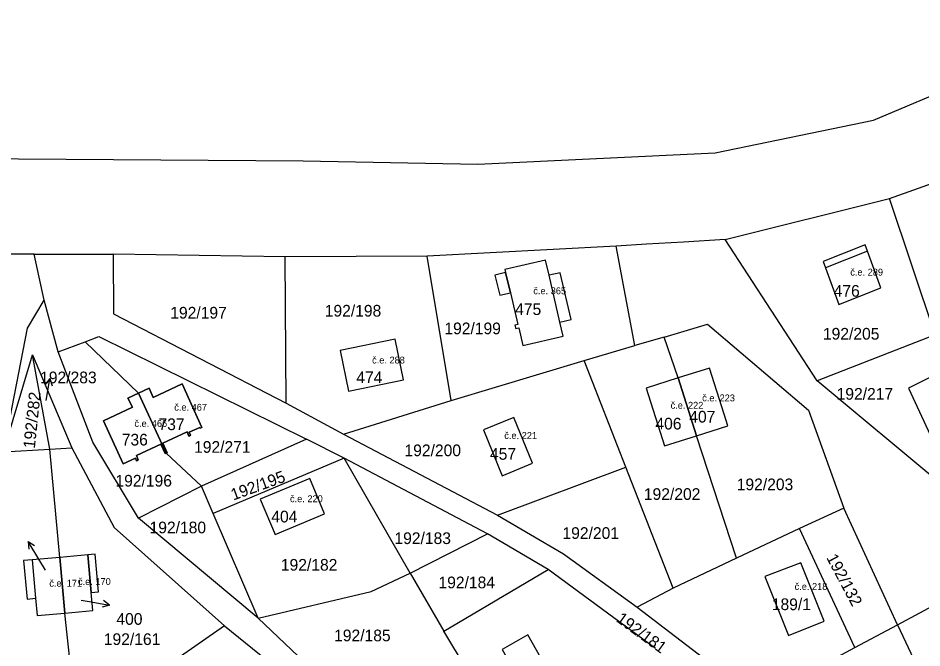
# Model space of a CAD drawing. Extents: x -887272 to -880188, y -1026687 to -1021896.
# Drawn here: x -882333.3 to -882201.9, y -1024111.9 to -1024020.3 of the extents above; entities that cross this region are included whole.
import ezdxf

# ---------------------------------------------------------------- set-up
doc = ezdxf.new("R2010")
doc.units = 0
for name, color, linetype in [('Definiční body', 7, 'Continuous'), ('Hranice parcel', 7, 'Continuous'), ('Parcelní čísla', 7, 'Continuous'), ('Polygon budovy', 7, 'Continuous'), ('Pop  PČ popisy', 7, 'Continuous'), ('Vnitřní kresba', 7, 'Continuous')]:
    doc.layers.add(name, color=color, linetype=linetype)

msp = doc.modelspace()

# ---------------------------------------------------------------- linework, layer by layer
at = {"layer": 'Hranice parcel'}
for p, q in [((-882206.58, -1024046.52), (-882188.26, -1024039.89)), ((-882230.46, -1024052.45), (-882206.58, -1024046.52)), ((-882199.93, -1024066.33), (-882206.58, -1024046.52)), ((-882217.07, -1024073.03), (-882230.46, -1024052.45)), ((-882246.33, -1024053.44), (-882273.78, -1024054.86)), ((-882243.61, -1024067.89), (-882246.33, -1024053.44)), ((-882330.93, -1024054.59), (-882336.63, -1024054.59)), ((-882330.93, -1024054.59), (-882319.43, -1024054.58)), ((-882329.46, -1024061.27), (-882330.93, -1024054.59)), ((-882294.43, -1024054.96), (-882319.43, -1024054.58)), ((-882273.78, -1024054.86), (-882294.43, -1024054.96)), ((-882294.27, -1024076.26), (-882294.43, -1024054.96)), ((-882270.28, -1024075.87), (-882273.78, -1024054.86)), ((-882327.43, -1024068.82), (-882329.46, -1024061.27)), ((-882239.34, -1024066.64), (-882243.61, -1024067.89)), ((-882237.27, -1024072.6), (-882239.34, -1024066.64)), ((-882199.93, -1024066.33), (-882217.07, -1024073.03)), ((-882327.43, -1024068.82), (-882323.51, -1024067.33)), ((-882315.74, -1024074.82), (-882323.51, -1024067.33)), ((-882250.94, -1024070.04), (-882243.61, -1024067.89)), ((-882335.35, -1024083.33), (-882331.18, -1024069.25)), ((-882328.64, -1024082.94), (-882331.18, -1024069.25)), ((-882331.18, -1024069.25), (-882325.42, -1024082.75)), ((-882270.28, -1024075.87), (-882250.94, -1024070.04)), ((-882244.88, -1024085.57), (-882250.94, -1024070.04)), ((-882237.27, -1024072.6), (-882234.62, -1024081)), ((-882196.2, -1024090.44), (-882217.07, -1024073.03)), ((-882311.73, -1024083.54), (-882315.74, -1024074.82)), ((-882285.96, -1024080.75), (-882270.28, -1024075.87)), ((-882294.27, -1024076.26), (-882285.96, -1024080.75)), ((-882291.31, -1024081.48), (-882306.6, -1024088.34)), ((-882285.87, -1024084.26), (-882291.31, -1024081.48)), ((-882285.96, -1024080.75), (-882263.54, -1024092.56)), ((-882228.8, -1024098.78), (-882234.62, -1024081)), ((-882328.64, -1024082.94), (-882325.42, -1024082.75)), ((-882335.35, -1024083.33), (-882328.64, -1024082.94)), ((-882327.16, -1024098.69), (-882328.64, -1024082.94)), ((-882306.6, -1024088.34), (-882311.73, -1024083.54)), ((-882285.87, -1024084.26), (-882304.9, -1024092.29)), ((-882276.26, -1024100.98), (-882285.87, -1024084.26)), ((-882265.03, -1024095.27), (-882285.87, -1024084.26)), ((-882263.54, -1024092.56), (-882244.88, -1024085.57)), ((-882238.02, -1024103.14), (-882244.88, -1024085.57)), ((-882306.6, -1024088.34), (-882315.76, -1024092.99)), ((-882304.9, -1024092.29), (-882306.6, -1024088.34)), ((-882213.21, -1024091.51), (-882219.65, -1024094.51)), ((-882205.42, -1024108.48), (-882213.21, -1024091.51)), ((-882298.33, -1024107.54), (-882315.76, -1024092.99)), ((-882298.33, -1024107.54), (-882304.9, -1024092.29)), ((-882219.65, -1024094.51), (-882228.8, -1024098.78)), ((-882211.61, -1024111.8), (-882219.65, -1024094.51)), ((-882276.26, -1024100.98), (-882265.03, -1024095.27)), ((-882256.19, -1024100.43), (-882265.03, -1024095.27)), ((-882326.44, -1024106.78), (-882327.16, -1024098.69)), ((-882228.8, -1024098.78), (-882238.02, -1024103.14)), ((-882276.26, -1024100.98), (-882271.37, -1024109.4)), ((-882271.37, -1024109.4), (-882256.19, -1024100.43)), ((-882240.6, -1024111.96), (-882256.19, -1024100.43)), ((-882238.02, -1024103.14), (-882243.24, -1024105.91)), ((-882205.42, -1024108.48), (-882198.92, -1024105.01)), ((-882325.37, -1024116.79), (-882326.44, -1024106.78)), ((-882273.27, -1024131.24), (-882298.33, -1024107.54)), ((-882303.23, -1024108.62), (-882310.26, -1024113.56)), ((-882211.61, -1024111.8), (-882205.42, -1024108.48)), ((-882262.64, -1024123.91), (-882271.37, -1024109.4)), ((-882222.5, -1024117.62), (-882211.61, -1024111.8))]:
    msp.add_line(p, q, dxfattribs=at)
for points in [[(-882340.1, -1024040.68), (-882291.8, -1024041.02), (-882266.44, -1024041.52), (-882231.92, -1024039.84), (-882208.92, -1024035.12), (-882179.22, -1024022.58), (-882174.49, -1024020.26)], [(-882230.46, -1024052.45), (-882236.52, -1024052.83), (-882241.91, -1024053.16), (-882246.33, -1024053.44)], [(-882209.75, -1024054.18), (-882210.09, -1024053.25), (-882216.22, -1024055.64), (-882215.88, -1024056.58), (-882213.96, -1024061.89), (-882207.81, -1024059.49), (-882209.75, -1024054.18)], [(-882319.43, -1024054.58), (-882319.38, -1024063.28), (-882294.27, -1024076.26)], [(-882254.49, -1024064.48), (-882252.87, -1024064.11), (-882254.44, -1024057.3), (-882256.06, -1024057.67), (-882256.57, -1024055.46), (-882262.49, -1024056.83), (-882262.38, -1024057.28), (-882263.95, -1024057.65), (-882263.24, -1024060.57), (-882261.69, -1024060.21), (-882260.59, -1024064.83), (-882261.03, -1024064.93), (-882260.91, -1024065.39), (-882260.48, -1024065.29)], [(-882335.35, -1024083.33), (-882331.89, -1024065.34), (-882329.46, -1024061.27)], [(-882260.48, -1024065.29), (-882259.87, -1024067.88), (-882254.02, -1024066.51), (-882254.49, -1024064.48)], [(-882239.34, -1024066.64), (-882233.03, -1024064.79), (-882218.36, -1024077.29), (-882213.21, -1024091.51)], [(-882186.22, -1024065.24), (-882203.83, -1024074.1), (-882196.2, -1024090.44)], [(-882323.51, -1024067.33), (-882321.51, -1024066.57), (-882291.31, -1024081.48)], [(-882277.2, -1024072.86), (-882278.42, -1024066.96), (-882286.44, -1024068.58), (-882285.22, -1024074.5), (-882277.2, -1024072.86)], [(-882315.76, -1024092.99), (-882322.4, -1024081.92), (-882327.43, -1024068.82)], [(-882234.62, -1024081), (-882230.09, -1024079.57), (-882230.63, -1024077.85), (-882232.74, -1024071.17), (-882237.27, -1024072.6)], [(-882315.74, -1024074.82), (-882314.2, -1024074.1), (-882313.61, -1024075.43), (-882309.42, -1024073.47), (-882306.56, -1024079.78), (-882306.8, -1024079.89), (-882306.84, -1024079.8), (-882308.37, -1024080.5), (-882308.17, -1024080.93), (-882308.41, -1024081.04), (-882308.68, -1024080.43), (-882312.23, -1024082.1), (-882311.6, -1024083.48), (-882311.73, -1024083.54)], [(-882237.27, -1024072.6), (-882241.95, -1024074.08), (-882239.3, -1024082.48), (-882234.62, -1024081)], [(-882311.73, -1024083.54), (-882311.85, -1024083.6), (-882312.48, -1024082.24), (-882316.05, -1024083.89), (-882315.78, -1024084.51), (-882316.02, -1024084.63), (-882316.19, -1024084.28), (-882317.96, -1024085.1), (-882320.82, -1024078.81), (-882316.64, -1024076.85), (-882317.29, -1024075.54), (-882315.74, -1024074.82)], [(-882262.9, -1024086.81), (-882258.46, -1024085), (-882261.17, -1024078.35), (-882265.61, -1024080.16), (-882262.9, -1024086.81)], [(-882325.42, -1024082.75), (-882319.29, -1024094.33), (-882303.23, -1024108.62)], [(-882290.85, -1024087.22), (-882298.05, -1024090.21), (-882295.9, -1024095.38), (-882288.71, -1024092.37), (-882290.85, -1024087.22)], [(-882263.54, -1024092.56), (-882253.97, -1024098.18), (-882243.24, -1024105.91)], [(-882326.44, -1024106.78), (-882322.41, -1024106.42), (-882322.64, -1024103.78), (-882321.55, -1024103.68), (-882322.03, -1024098.23), (-882323.13, -1024098.33), (-882327.16, -1024098.69)], [(-882327.16, -1024098.69), (-882331.2, -1024099.05), (-882332.45, -1024099.16), (-882331.95, -1024104.74), (-882330.7, -1024104.63), (-882330.48, -1024107.14), (-882326.44, -1024106.78)], [(-882224.69, -1024101.49), (-882221.25, -1024110.05), (-882216.06, -1024107.94), (-882219.46, -1024099.5), (-882224.69, -1024101.49)], [(-882298.33, -1024107.54), (-882281.94, -1024103.67), (-882276.26, -1024100.98)], [(-882243.24, -1024105.91), (-882225.71, -1024119.34), (-882222.5, -1024117.62)], [(-882303.23, -1024108.62), (-882291.29, -1024118.32), (-882280.53, -1024129.66)], [(-882205.42, -1024108.48), (-882196.11, -1024128.27), (-882209.58, -1024135.28)], [(-882259.17, -1024109.96), (-882262.9, -1024112.1), (-882260.34, -1024116.56), (-882259.77, -1024117.56), (-882256.04, -1024115.42), (-882256.61, -1024114.42), (-882259.17, -1024109.96)]]:
    msp.add_lwpolyline(points, dxfattribs=at)
at = {"layer": 'Polygon budovy'}
for points in [[(-882207.81, -1024059.49), (-882209.75, -1024054.18), (-882215.88, -1024056.58), (-882213.96, -1024061.89)], [(-882254.49, -1024064.48), (-882256.06, -1024057.67), (-882256.57, -1024055.46), (-882262.49, -1024056.83), (-882262.38, -1024057.28), (-882261.69, -1024060.21), (-882260.59, -1024064.83), (-882261.03, -1024064.93), (-882260.91, -1024065.39), (-882260.48, -1024065.29), (-882259.87, -1024067.88), (-882254.02, -1024066.51)], [(-882286.44, -1024068.58), (-882285.22, -1024074.5), (-882277.2, -1024072.86), (-882278.42, -1024066.96)], [(-882234.62, -1024081), (-882230.09, -1024079.57), (-882230.63, -1024077.85), (-882232.74, -1024071.17), (-882237.27, -1024072.6)], [(-882314.2, -1024074.1), (-882315.74, -1024074.82), (-882311.73, -1024083.54), (-882311.6, -1024083.48), (-882312.23, -1024082.1), (-882308.68, -1024080.43), (-882308.41, -1024081.04), (-882308.17, -1024080.93), (-882308.37, -1024080.5), (-882306.84, -1024079.8), (-882306.8, -1024079.89), (-882306.56, -1024079.78), (-882309.42, -1024073.47), (-882313.61, -1024075.43)], [(-882234.62, -1024081), (-882237.27, -1024072.6), (-882241.95, -1024074.08), (-882239.3, -1024082.48)], [(-882320.82, -1024078.81), (-882317.96, -1024085.1), (-882316.19, -1024084.28), (-882316.02, -1024084.63), (-882315.78, -1024084.51), (-882316.05, -1024083.89), (-882312.48, -1024082.24), (-882311.85, -1024083.6), (-882311.73, -1024083.54), (-882315.74, -1024074.82), (-882317.29, -1024075.54), (-882316.64, -1024076.85)], [(-882261.17, -1024078.35), (-882265.61, -1024080.16), (-882262.9, -1024086.81), (-882258.46, -1024085)], [(-882298.05, -1024090.21), (-882295.9, -1024095.38), (-882288.71, -1024092.37), (-882290.85, -1024087.22)], [(-882326.44, -1024106.78), (-882322.41, -1024106.42), (-882322.64, -1024103.78), (-882323.13, -1024098.33), (-882327.16, -1024098.69)], [(-882330.48, -1024107.14), (-882326.44, -1024106.78), (-882327.16, -1024098.69), (-882331.2, -1024099.05), (-882330.7, -1024104.63)], [(-882216.06, -1024107.94), (-882219.46, -1024099.5), (-882224.69, -1024101.49), (-882221.25, -1024110.05)], [(-882256.61, -1024114.42), (-882259.17, -1024109.96), (-882262.9, -1024112.1), (-882260.34, -1024116.56)]]:
    msp.add_lwpolyline(points, close=True, dxfattribs=at)
at = {"layer": 'Pop  PČ popisy'}
for p, q in [((-882328.65, -1024072.66), (-882329.3, -1024073.57)), ((-882329.12, -1024075.62), (-882328.65, -1024072.66)), ((-882328.65, -1024072.66), (-882328.31, -1024073.72)), ((-882329.16, -1024075.86), (-882329.12, -1024075.62)), ((-882330.25, -1024098.95), (-882331.8, -1024096.38)), ((-882331.8, -1024096.38), (-882330.85, -1024096.98)), ((-882331.8, -1024096.38), (-882331.71, -1024097.49)), ((-882329.28, -1024100.57), (-882330.25, -1024098.95)), ((-882324.09, -1024104.89), (-882322.91, -1024105.1)), ((-882322.91, -1024105.1), (-882319.96, -1024105.62)), ((-882319.96, -1024105.62), (-882320.85, -1024104.95)), ((-882319.96, -1024105.62), (-882321.03, -1024105.94))]:
    msp.add_line(p, q, dxfattribs=at)
at = {"layer": 'Vnitřní kresba'}
for p, q in [((-882209.75, -1024054.18), (-882215.88, -1024056.58)), ((-882261.69, -1024060.21), (-882262.38, -1024057.28)), ((-882254.49, -1024064.48), (-882256.06, -1024057.67)), ((-882323.13, -1024098.33), (-882322.64, -1024103.78)), ((-882331.2, -1024099.05), (-882330.7, -1024104.63))]:
    msp.add_line(p, q, dxfattribs=at)

# ---------------------------------------------------------------- texts
at = {"layer": 'Definiční body'}
for s, p in [('č.e. 289', (-882212.27, -1024057.71)), ('č.e. 365', (-882258.35, -1024060.42)), ('č.e. 288', (-882281.79, -1024070.49)), ('č.e. 222', (-882238.39, -1024077.07)), ('č.e. 223', (-882233.8, -1024076)), ('č.e. 467', (-882310.55, -1024077.36)), ('č.e. 466', (-882316.34, -1024079.71)), ('č.e. 221', (-882262.57, -1024081.46)), ('č.e. 220', (-882293.72, -1024090.66)), ('č.e. 171', (-882328.71, -1024102.95)), ('č.e. 170', (-882324.54, -1024102.7)), ('č.e. 218', (-882220.36, -1024103.42))]:
    msp.add_text(s, height=1, dxfattribs=at).set_placement(p)
at = {"layer": 'Parcelní čísla'}
for s, p in [('476', (-882214.69, -1024060.78)), ('475', (-882260.99, -1024063.44)), ('192/197', (-882311.13, -1024063.96)), ('192/198', (-882288.67, -1024063.67)), ('192/199', (-882271.28, -1024066.24)), ('192/205', (-882216.25, -1024067.02)), ('192/283', (-882330.05, -1024073.37)), ('474', (-882284.08, -1024073.35)), ('192/217', (-882214.26, -1024075.76)), ('407', (-882235.68, -1024079.08)), ('737', (-882312.84, -1024080.18)), ('406', (-882240.6, -1024080.09)), ('736', (-882318.18, -1024082.42)), ('192/271', (-882307.67, -1024083.48)), ('192/200', (-882277.08, -1024083.97)), ('457', (-882264.65, -1024084.49)), ('192/196', (-882319.1, -1024088.39)), ('192/203', (-882228.78, -1024088.92)), ('192/202', (-882242.28, -1024090.33)), ('404', (-882296.44, -1024093.6)), ('192/180', (-882314.14, -1024095.19)), ('192/201', (-882254.11, -1024096)), ('192/183', (-882278.54, -1024096.75)), ('192/182', (-882295.05, -1024100.62)), ('192/184', (-882272.14, -1024103.18)), ('189/1', (-882223.68, -1024106.36)), ('400', (-882318.96, -1024108.49)), ('192/161', (-882320.79, -1024111.43)), ('192/185', (-882287.31, -1024110.89))]:
    msp.add_text(s, height=1.7, dxfattribs=at).set_placement(p)
for s, rotation, p in [('192/282', 84, (-882330.82, -1024082.9)), ('192/195', 20, (-882301.96, -1024090.43)), ('192/132', 298, (-882215.8, -1024098.72)), ('192/181', 324, (-882246.42, -1024107.91))]:
    msp.add_text(s, height=1.7, rotation=rotation, dxfattribs=at).set_placement(p)

doc.saveas('drawing.dxf')
